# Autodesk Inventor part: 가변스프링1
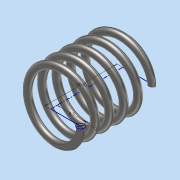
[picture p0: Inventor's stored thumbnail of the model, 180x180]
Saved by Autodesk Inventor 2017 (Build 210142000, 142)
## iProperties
Part Number: 가변스프링1
Material: 스테인레스 스틸
Document SubType Name: Modeling
Designer: MRC
Density: 8 g/cm^3
Appearance: 반연마
Mass: 6.57245 g
Surface Area: 16.7217 cm^2
Volume: 0.821556 cm^3
Author: MRC
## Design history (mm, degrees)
sketch "스케치1"
  geometry: L1 (0, 0)-(0, 20.5); L2 (0, 0)-(8.5, 0); L3 (0, 20.5)-(8.5, 20.5); C1 r 1 at (8.5, 0)
  constraints: 6 end point, 2 horizontal, 1 centre point, 1 coincident, 1 vertical
  dimensions: "d0" = 20.5 distance of L1.start L1.end (derived); "d1" = 8.5 distance of L1.start L2.end; "d2" = 2 diameter of C1
feature "코일1" pitch "d3" = 10; turns "d5" = 5; dims "d4" = 20.5 (= d0), "d6" = 0, angle "d7" = 90 deg, angle "d8" = 90 deg, "d9" = 0, "d10" = 0
sketch "스케치2"
  geometry: L1 (20.5, 13.489)-(0, 13.489); L2 (0, 13.489)-(0, -13.489); L3 (0, -13.489)-(20.5, -13.489); L4 (20.5, -13.489)-(20.5, 13.489); 2 further points
  constraints: 8 end point, 2 parallel, 1 coincident, 1 horizontal, 1 midpoint, 1 perpendicular
  dimensions: "d11" = 20.5 distance of L2.end L3.end (= d0)
extrude "돌출1" sketch "스케치2" stored distance "d12" = 0; taper "d13" = 0 deg
node "솔리드1"
